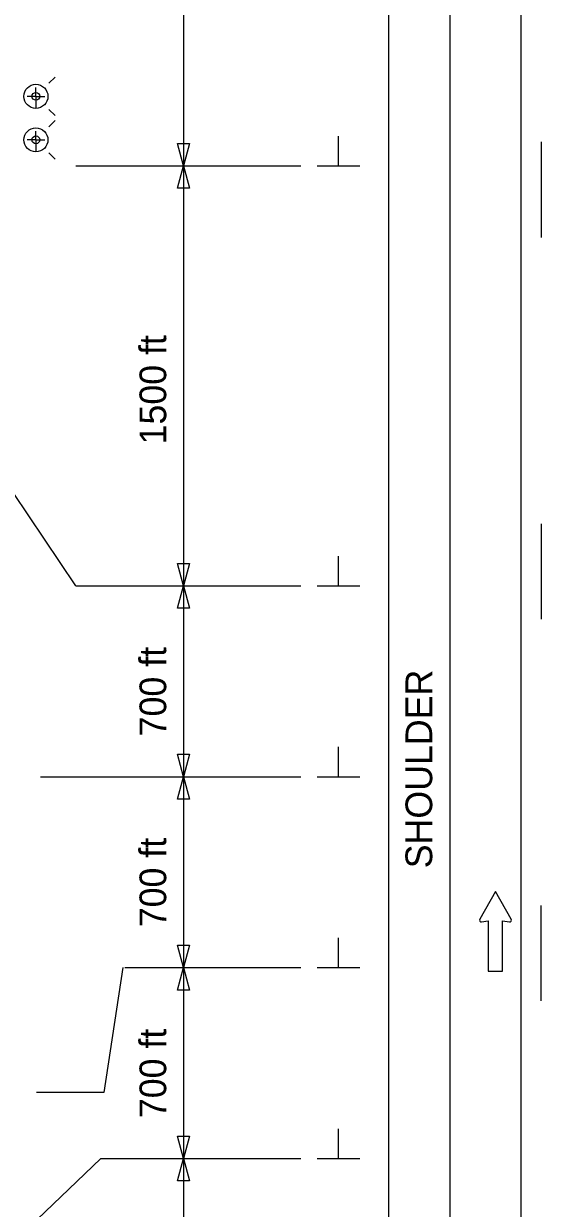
# Model space of a CAD drawing. Extents: x 15278 to 18126, y 1908 to 6555.
# Drawn here: x 16480.8 to 16616.4, y 2485.4 to 2795.7 of the extents above; entities that cross this region are included whole.
import ezdxf

# ---------------------------------------------------------------- set-up
doc = ezdxf.new("R2010")
doc.units = 0
for name, color, linetype in [('ALI_LEGAL_EX', 7, 'Continuous'), ('MT_SCRATCH_LEVEL_E', 7, 'Continuous'), ('PAVT_EDGE_EX', 7, 'Continuous'), ('TRAFFIC_SIGNS_PR', 7, 'Continuous'), ('TYPICAL_TEXT_DIMEN_PR', 7, 'Continuous')]:
    doc.layers.add(name, color=color, linetype=linetype)

msp = doc.modelspace()

# ---------------------------------------------------------------- linework, layer by layer
at = {"layer": 'ALI_LEGAL_EX'}
msp.add_line((16610.98, 3236.46), (16610.98, 2407.28), dxfattribs=at)
for points in [[(16616.35, 2764.74), (16616.35, 2739.74)], [(16616.35, 2664.74), (16616.35, 2639.74)], [(16616.35, 2539.74), (16616.35, 2564.74)], [(16616.35, 2539.74), (16616.35, 2564.74)]]:
    msp.add_lwpolyline(points, dxfattribs=at)
at = {"layer": 'MT_SCRATCH_LEVEL_E'}
for p, q in [((16604.32, 2568.38), (16600.21, 2561.14)), ((16608.47, 2561.14), (16604.32, 2568.38)), ((16600.69, 2560.45), (16602.47, 2560.77)), ((16602.47, 2560.77), (16602.47, 2547.51)), ((16606.21, 2547.51), (16606.21, 2560.77)), ((16606.21, 2560.77), (16607.99, 2560.45)), ((16602.47, 2547.51), (16606.21, 2547.51))]:
    msp.add_line(p, q, dxfattribs=at)
for centre, start, end in [((16600.62, 2560.91), 150.4248, 279.9638), ((16608.06, 2560.91), 260.0362, 29.7731)]:
    msp.add_arc(centre, 0.463, start, end, dxfattribs=at)
at = {"layer": 'PAVT_EDGE_EX'}
for p, q in [((16576.35, 3138.78), (16576.35, 2305.55)), ((16592.35, 3138.78), (16592.35, 2305.55))]:
    msp.add_line(p, q, dxfattribs=at)
at = {"layer": 'TRAFFIC_SIGNS_PR'}
for p, q in [((16487.39, 2780.1), (16489.02, 2781.72)), ((16483.96, 2776.67), (16483.96, 2778.97)), ((16483.96, 2776.67), (16481.66, 2776.67)), ((16483.96, 2776.67), (16483.96, 2773.52)), ((16483.96, 2776.67), (16486.27, 2776.67)), ((16489.01, 2771.62), (16487.39, 2773.25)), ((16483.96, 2765.28), (16483.96, 2767.58)), ((16487.39, 2768.7), (16489.02, 2770.33)), ((16483.96, 2765.28), (16481.66, 2765.28)), ((16483.96, 2765.28), (16483.96, 2762.13)), ((16483.96, 2765.28), (16486.27, 2765.28)), ((16489.01, 2760.23), (16487.39, 2761.86))]:
    msp.add_line(p, q, dxfattribs=at)
for centre, radius in [((16483.96, 2776.67), 3.15), ((16483.96, 2776.67), 1.02), ((16483.96, 2765.28), 3.15), ((16483.96, 2765.28), 1.02)]:
    msp.add_circle(centre, radius, dxfattribs=at)
at = {"layer": 'TYPICAL_TEXT_DIMEN_PR'}
for p, q in [((16522.62, 2868.48), (16522.62, 2758.48)), ((16563.23, 2758.48), (16563.23, 2766.26)), ((16522.62, 2758.48), (16521.06, 2764.34)), ((16521.06, 2764.34), (16522.62, 2764.34)), ((16522.62, 2764.34), (16524.19, 2764.34)), ((16524.19, 2764.34), (16522.62, 2758.48)), ((16494.38, 2758.48), (16553.35, 2758.48)), ((16521.06, 2752.61), (16522.62, 2758.48)), ((16521.06, 2752.61), (16522.62, 2758.48)), ((16522.62, 2758.48), (16522.62, 2648.48)), ((16522.62, 2758.48), (16524.19, 2752.61)), ((16522.62, 2758.48), (16524.19, 2752.61)), ((16557.6, 2758.48), (16568.85, 2758.48)), ((16522.62, 2752.61), (16521.06, 2752.61)), ((16522.62, 2752.61), (16521.06, 2752.61)), ((16524.19, 2752.61), (16522.62, 2752.61)), ((16524.19, 2752.61), (16522.62, 2752.61)), ((16494.38, 2648.48), (16459.72, 2700.07)), ((16563.23, 2648.48), (16563.23, 2656.26)), ((16522.62, 2648.48), (16521.06, 2654.34)), ((16521.06, 2654.34), (16522.62, 2654.34)), ((16522.62, 2648.48), (16521.06, 2654.34)), ((16521.06, 2654.34), (16522.62, 2654.34)), ((16522.62, 2654.34), (16524.19, 2654.34)), ((16524.19, 2654.34), (16522.62, 2648.48)), ((16522.62, 2654.34), (16524.19, 2654.34)), ((16524.19, 2654.34), (16522.62, 2648.48)), ((16494.38, 2648.48), (16553.35, 2648.48)), ((16521.05, 2642.61), (16522.62, 2648.48)), ((16522.62, 2648.48), (16522.62, 2598.48)), ((16522.62, 2648.48), (16524.2, 2642.61)), ((16557.6, 2648.48), (16568.85, 2648.48)), ((16522.62, 2642.61), (16521.05, 2642.61)), ((16524.2, 2642.61), (16522.62, 2642.61)), ((16563.23, 2598.48), (16563.23, 2606.26)), ((16522.62, 2598.48), (16521.05, 2604.34)), ((16521.05, 2604.34), (16522.62, 2604.34)), ((16522.62, 2604.34), (16524.2, 2604.34)), ((16524.2, 2604.34), (16522.62, 2598.48)), ((16485.14, 2598.48), (16553.35, 2598.48)), ((16521.05, 2592.61), (16522.62, 2598.48)), ((16522.62, 2598.48), (16522.62, 2548.48)), ((16522.62, 2598.48), (16524.2, 2592.61)), ((16557.6, 2598.48), (16568.85, 2598.48)), ((16522.62, 2592.61), (16521.05, 2592.61)), ((16524.2, 2592.61), (16522.62, 2592.61)), ((16522.62, 2548.48), (16521.05, 2554.34)), ((16521.05, 2554.34), (16522.62, 2554.34)), ((16522.62, 2554.34), (16524.2, 2554.34)), ((16524.2, 2554.34), (16522.62, 2548.48)), ((16563.23, 2548.48), (16563.23, 2556.26)), ((16506.71, 2548.48), (16501.79, 2515.74)), ((16507.24, 2548.48), (16553.35, 2548.48)), ((16521.05, 2542.61), (16522.62, 2548.48)), ((16522.62, 2548.48), (16522.62, 2498.48)), ((16522.62, 2548.48), (16524.2, 2542.61)), ((16557.6, 2548.48), (16568.85, 2548.48)), ((16522.62, 2542.61), (16521.05, 2542.61)), ((16524.2, 2542.61), (16522.62, 2542.61)), ((16501.79, 2515.74), (16484.13, 2515.74)), ((16522.62, 2498.48), (16521.05, 2504.34)), ((16521.05, 2504.34), (16522.62, 2504.34)), ((16522.62, 2504.34), (16524.2, 2504.34)), ((16524.2, 2504.34), (16522.62, 2498.48)), ((16563.23, 2498.48), (16563.23, 2506.26)), ((16500.94, 2498.48), (16438.49, 2438.78)), ((16500.94, 2498.48), (16553.35, 2498.48)), ((16521.05, 2492.61), (16522.62, 2498.48)), ((16522.62, 2498.48), (16522.62, 2448.48)), ((16522.62, 2498.48), (16524.2, 2492.61)), ((16557.6, 2498.48), (16568.85, 2498.48)), ((16522.62, 2492.61), (16521.05, 2492.61)), ((16524.2, 2492.61), (16522.62, 2492.61))]:
    msp.add_line(p, q, dxfattribs=at)

# ---------------------------------------------------------------- texts
for s, p in [('1500 ft', (16518.1, 2685.51)), ('700 ft', (16518.1, 2609.05)), ('SHOULDER', (16587.77, 2574.49)), ('700 ft', (16518.1, 2559.05)), ('700 ft', (16518.1, 2509.05))]:
    msp.add_text(s, height=7, rotation=90, dxfattribs=at).set_placement(p)

doc.saveas('drawing.dxf')
